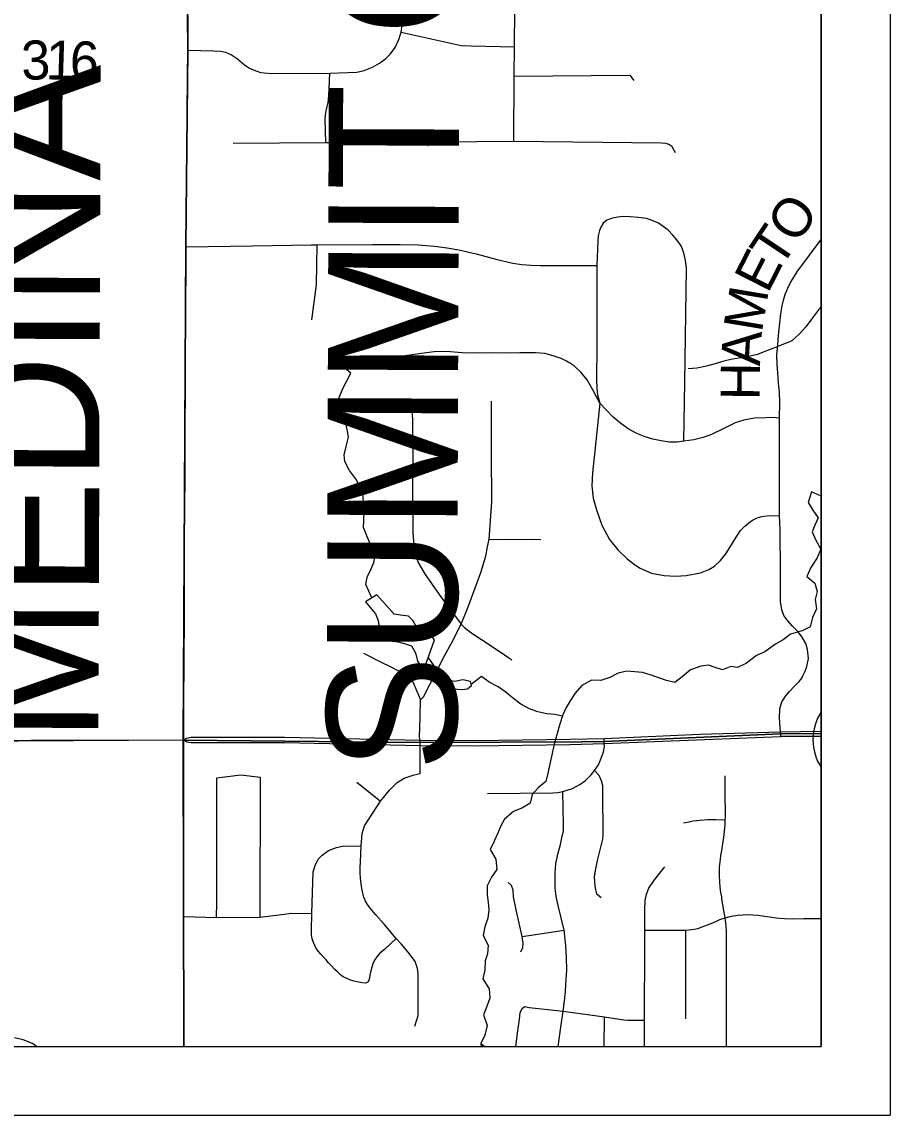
# Model space of a CAD drawing. Extents: x 0 to 34, y 0 to 22.
# Drawn here: x 7.738 to 9, y 14 to 15.589 of the extents above; entities that cross this region are included whole.
import ezdxf

# ---------------------------------------------------------------- set-up
doc = ezdxf.new("R2010")
doc.units = 0
for name, color, linetype in [('GM_X_Corporation', 7, 'Continuous'), ('GM_X_County_Road', 7, 'Continuous'), ('GM_X_County_Road_Text', 7, 'Continuous'), ('GM_X_County_Text', 7, 'Continuous'), ('GM_X_Minor_Lake', 7, 'Continuous'), ('GM_X_Minor_River', 7, 'Continuous'), ('GM_X_State_Route', 7, 'Continuous'), ('GM_X_State_Shield', 7, 'Continuous'), ('GM_X_Township_Road', 7, 'Continuous'), ('GM_X_Township_Road_Text', 7, 'Continuous'), ('SH_Data', 7, 'Continuous')]:
    doc.layers.add(name, color=color, linetype=linetype)

msp = doc.modelspace()

# ---------------------------------------------------------------- linework, layer by layer
at = {"layer": 'GM_X_Corporation'}
for points in [[(2.1, 20.9), (2.1, 14.1), (7.9734, 14.1), (7.9726, 14.5453), (7.9765, 15.2637), (7.9792, 15.5481), (7.979, 15.5988), (7.9808, 15.7192), (7.9807, 15.9078), (7.9821, 16.2487), (7.9825, 16.3395), (7.9818, 16.3982), (7.9825, 16.6077), (7.9838, 16.7968), (7.9877, 17.3871), (7.9891, 17.5498), (7.991, 17.7727), (7.9901, 18.1613)], [(7.9901, 18.1613), (7.991, 17.7727), (7.9891, 17.5498), (7.9877, 17.3871), (7.9838, 16.7968), (7.9825, 16.6077), (7.9818, 16.3982), (7.9825, 16.3395), (7.9821, 16.2487), (7.9807, 15.9078), (7.9808, 15.7192), (7.979, 15.5988), (7.9792, 15.5481), (7.9765, 15.2637), (7.9726, 14.5453), (7.9734, 14.1), (8.9, 14.1), (8.9, 20.9)], [(7.9901, 18.1613), (7.991, 17.7727), (7.9891, 17.5498), (7.9877, 17.3871), (7.9838, 16.7968), (7.9825, 16.6077), (7.9818, 16.3982), (7.9825, 16.3395), (7.9821, 16.2487), (7.9807, 15.9078), (7.9808, 15.7192), (7.979, 15.5988), (7.9792, 15.5481), (7.9765, 15.2637), (7.9726, 14.5453), (8.3169, 14.5418), (8.5518, 14.5426), (8.5844, 14.5431), (8.8409, 14.5545), (8.9, 14.5547), (8.9, 19.1229)], [(7.9901, 18.1613), (7.991, 17.7727), (7.9891, 17.5498), (7.9877, 17.3871), (7.9838, 16.7968), (7.9825, 16.6077), (7.9818, 16.3982), (7.9825, 16.3395), (7.9821, 16.2487), (7.9807, 15.9078), (7.9808, 15.7192), (7.979, 15.5988), (7.9792, 15.5481), (7.9765, 15.2637), (7.9726, 14.5453), (7.0871, 14.5429), (7.0197, 14.5427), (6.4941, 14.5412), (6.1476, 14.5397), (5.4644, 14.5374), (4.5212, 14.531)]]:
    msp.add_lwpolyline(points, dxfattribs=at)
for points in [[(2.8649, 14.1), (7.9734, 14.1), (7.9726, 14.5453), (7.0871, 14.5429), (7.0197, 14.5427), (6.4941, 14.5412), (6.1476, 14.5397), (5.4644, 14.5374), (4.5212, 14.531), (4.3772, 14.5296), (4.3422, 14.5307), (3.735, 14.5275), (3.3839, 14.5264), (3.3511, 14.525), (2.8655, 14.5214), (2.8638, 14.4461)], [(7.9734, 14.1), (8.9, 14.1), (8.9, 14.5547), (8.8409, 14.5545), (8.5844, 14.5431), (8.5518, 14.5426), (8.3169, 14.5418), (7.9726, 14.5453)]]:
    msp.add_lwpolyline(points, close=True, dxfattribs=at)
at = {"layer": 'GM_X_County_Road'}
for p, q in [((7.9798, 15.5778), (7.9801, 15.5987)), ((7.9793, 15.5479), (7.9798, 15.5778)), ((8.9, 14.5511), (8.8414, 14.5504))]:
    msp.add_line(p, q, dxfattribs=at)
for points in [[(7.9771, 15.2624), (7.9772, 15.2803), (7.9775, 15.328), (7.9777, 15.3954), (7.9782, 15.4454), (7.9783, 15.4576), (7.9788, 15.5089), (7.9793, 15.547), (7.9793, 15.5479)], [(8.8405, 14.7895), (8.8401, 14.8508), (8.8394, 14.8716), (8.8394, 15.0133), (8.8396, 15.0358), (8.8394, 15.0508), (8.8378, 15.0639), (8.8366, 15.0796), (8.8357, 15.0907), (8.8353, 15.1059), (8.8364, 15.1146), (8.8383, 15.1386), (8.8399, 15.1515), (8.8412, 15.1648), (8.8433, 15.1764), (8.8456, 15.1865), (8.8479, 15.1943), (8.8512, 15.2019), (8.8551, 15.2105), (8.8657, 15.2273), (8.9, 15.2729)], [(7.9738, 14.5455), (7.9738, 14.5968), (7.9742, 14.663), (7.9746, 14.723), (7.9746, 14.8291), (7.975, 14.8866), (7.9753, 14.9251), (7.9755, 14.9636), (7.9757, 15.0018), (7.9759, 15.0507), (7.9762, 15.1178), (7.9764, 15.1774), (7.9768, 15.2327), (7.9771, 15.2582), (7.9771, 15.2624)], [(8.8731, 14.6384), (8.8765, 14.6453), (8.879, 14.652), (8.8813, 14.6639), (8.8797, 14.6769), (8.8774, 14.6857), (8.8723, 14.6949), (8.8659, 14.7029), (8.8576, 14.7112), (8.8512, 14.7184), (8.8454, 14.7264), (8.8424, 14.7347), (8.8408, 14.7465), (8.8405, 14.7895)], [(8.8414, 14.5504), (8.8411, 14.5539), (8.8409, 14.5574), (8.8393, 14.5772), (8.8396, 14.5905), (8.8428, 14.601), (8.8484, 14.6096), (8.8539, 14.6156), (8.8607, 14.6231), (8.8677, 14.6306), (8.8717, 14.6354), (8.8731, 14.6384)], [(7.9735, 14.5256), (7.9738, 14.5415), (7.9738, 14.5455)], [(7.9736, 14.2886), (7.9737, 14.459), (7.9734, 14.5147), (7.9735, 14.5256)], [(7.9737, 14.1), (7.9737, 14.191), (7.9735, 14.2656), (7.9735, 14.2825), (7.9736, 14.2886)]]:
    msp.add_lwpolyline(points, dxfattribs=at)
at = {"layer": 'GM_X_Minor_Lake'}
for points in [[(8.338, 14.6911), (8.3322, 14.6983), (8.3246, 14.7009), (8.3177, 14.7031), (8.312, 14.7091), (8.3066, 14.7189), (8.3001, 14.7253), (8.2883, 14.7268), (8.2792, 14.7282), (8.2539, 14.7564), (8.2377, 14.746), (8.2522, 14.7287), (8.2561, 14.7188), (8.2578, 14.7052), (8.2632, 14.6954), (8.2731, 14.6897), (8.2849, 14.688), (8.2959, 14.685), (8.3046, 14.6824), (8.3101, 14.6719), (8.3132, 14.6597), (8.317, 14.6541), (8.3232, 14.6499)], [(8.3232, 14.6499), (8.338, 14.6911)], [(8.3502, 14.6331), (8.3568, 14.621)], [(8.3568, 14.621), (8.3655, 14.6196), (8.3773, 14.6189), (8.386, 14.6198), (8.3917, 14.6244), (8.3901, 14.6304), (8.3791, 14.6326), (8.3673, 14.6306), (8.3502, 14.6331)]]:
    msp.add_lwpolyline(points, dxfattribs=at)
at = {"layer": 'GM_X_Minor_River'}
for q in [(8.4112, 14.1), (8.4056, 14.1)]:
    msp.add_line((8.4051, 14.104), q, dxfattribs=at)
for points in [[(8.9, 15.1748), (8.896, 15.1706), (8.8859, 15.1572), (8.8773, 15.1461), (8.8679, 15.1353), (8.857, 15.1254), (8.8415, 15.1195), (8.8294, 15.1145), (8.8177, 15.1102), (8.8071, 15.1055), (8.7965, 15.1031), (8.7836, 15.1007), (8.7684, 15.0983), (8.7582, 15.0959), (8.7438, 15.0916), (8.7332, 15.0889), (8.7192, 15.0857), (8.7063, 15.0848)], [(8.2466, 14.7518), (8.2382, 14.7715), (8.24, 14.7821), (8.2452, 14.7932), (8.2497, 14.8035), (8.2515, 14.813), (8.2461, 14.8263), (8.2395, 14.8422), (8.2348, 14.8543), (8.2351, 14.8646), (8.2357, 14.8775), (8.2349, 14.8889), (8.234, 14.8999), (8.2301, 14.9101), (8.2247, 14.9237), (8.2143, 14.9369), (8.2077, 14.9502), (8.2065, 14.9597), (8.2098, 14.9737), (8.2127, 14.9855), (8.2111, 14.9969), (8.2084, 15.0075), (8.2029, 15.0204), (8.1987, 15.0314), (8.1982, 15.0409), (8.2045, 15.0561), (8.2097, 15.0657), (8.2161, 15.0787), (8.2065, 15.0869), (8.2, 15.1002), (8.1964, 15.1119)], [(8.9, 14.9005), (8.8988, 14.9004), (8.8855, 14.906), (8.8807, 14.8908), (8.8877, 14.8794), (8.8953, 14.8681), (8.8905, 14.8574), (8.8868, 14.8479), (8.8918, 14.8358), (8.8992, 14.8226), (8.894, 14.8103), (8.885, 14.7962), (8.879, 14.7832), (8.8905, 14.7731), (8.894, 14.7613), (8.8911, 14.7495), (8.8931, 14.7362), (8.8872, 14.7233), (8.8839, 14.7096), (8.8722, 14.7041), (8.8551, 14.699), (8.8446, 14.691), (8.8336, 14.6844), (8.8178, 14.6736), (8.8057, 14.6682), (8.7914, 14.657), (8.7781, 14.6508), (8.7686, 14.6522), (8.7565, 14.6472), (8.7455, 14.6505), (8.736, 14.6542), (8.725, 14.6526), (8.7099, 14.6471), (8.6978, 14.6371), (8.6873, 14.6287), (8.6751, 14.632), (8.6625, 14.6364), (8.6526, 14.6398), (8.6401, 14.6434), (8.6173, 14.6455), (8.6048, 14.6423), (8.5927, 14.6361), (8.5798, 14.6318), (8.5662, 14.6321), (8.5522, 14.6247), (8.5421, 14.6136), (8.535, 14.6022), (8.5293, 14.5926), (8.5245, 14.5819), (8.5197, 14.5667), (8.516, 14.5549), (8.5112, 14.5374), (8.5087, 14.5259), (8.5051, 14.5084), (8.5032, 14.4989), (8.4996, 14.4848), (8.4883, 14.476), (8.4796, 14.466), (8.4771, 14.4534), (8.4658, 14.4465), (8.4525, 14.4414), (8.4397, 14.4303), (8.4341, 14.4204), (8.4293, 14.4089), (8.4248, 14.3982), (8.4189, 14.386), (8.427, 14.372), (8.4286, 14.3572), (8.4208, 14.3458), (8.4144, 14.3332), (8.4142, 14.3206), (8.4158, 14.3092), (8.4166, 14.2982), (8.4152, 14.2864), (8.4112, 14.2739), (8.4086, 14.2609), (8.4159, 14.2473), (8.4149, 14.2344), (8.4116, 14.2245), (8.411, 14.2108), (8.408, 14.1982), (8.4173, 14.1835), (8.4185, 14.1698), (8.413, 14.1557), (8.4089, 14.1458), (8.4143, 14.1303), (8.4111, 14.1162), (8.4051, 14.104)], [(8.3514, 14.6329), (8.3288, 14.6657)], [(8.524, 14.5802), (8.5127, 14.5822), (8.5013, 14.5836), (8.488, 14.5865), (8.477, 14.5902), (8.4633, 14.5973), (8.453, 14.6052), (8.44, 14.6157), (8.4304, 14.6225), (8.4174, 14.6292), (8.406, 14.6378), (8.3912, 14.6261)], [(7.7597, 14.1), (7.7536, 14.1039), (7.7403, 14.1096), (7.7274, 14.1122)]]:
    msp.add_lwpolyline(points, dxfattribs=at)
at = {"layer": 'GM_X_State_Route'}
for p, q in [((8.7427, 14.5464), (8.8414, 14.5504)), ((8.8414, 14.5504), (8.9, 14.5511))]:
    msp.add_line(p, q, dxfattribs=at)
for points in [[(7.9738, 14.5455), (7.9777, 14.5482), (7.9837, 14.5493), (8.1198, 14.5494), (8.3171, 14.545), (8.3964, 14.5445), (8.5344, 14.5463), (8.5845, 14.5476), (8.7235, 14.5538), (8.8409, 14.5574), (8.9, 14.5581)], [(7.1508, 14.5437), (7.2108, 14.5436), (7.591, 14.5434), (7.6249, 14.5436), (7.7079, 14.5441), (7.7327, 14.5443), (7.9738, 14.5455)], [(7.9738, 14.5455), (7.9778, 14.5427), (7.9837, 14.5417), (8.1199, 14.5419), (8.3172, 14.5374), (8.3965, 14.5369), (8.5345, 14.5388), (8.5846, 14.54), (8.7427, 14.5464)]]:
    msp.add_lwpolyline(points, dxfattribs=at)
at = {"layer": 'GM_X_State_Shield'}
msp.add_line((8.9, 14.5049), (8.9, 14.5864), dxfattribs=at)
msp.add_arc((8.9622, 14.5457), 0.0744, 146.7554, 213.2446, dxfattribs=at)
at = {"layer": 'GM_X_Township_Road'}
for p, q in [((8.2251, 14.4841), (8.2592, 14.4566)), ((8.4655, 14.2595), (8.5263, 14.2687)), ((8.5845, 14.1), (8.5851, 14.1427)), ((8.6432, 14.1), (8.6432, 14.138))]:
    msp.add_line(p, q, dxfattribs=at)
for points in [[(8.4531, 15.4157), (8.4538, 15.5102), (8.454, 15.5528), (8.4547, 15.6078), (8.4549, 15.7237), (8.4568, 15.806)], [(7.9793, 15.5479), (8.017, 15.547), (8.0271, 15.5466), (8.0343, 15.545), (8.043, 15.5415), (8.0516, 15.5357), (8.0617, 15.527), (8.069, 15.5219), (8.0757, 15.5189), (8.0852, 15.5157), (8.1006, 15.5141), (8.1856, 15.5145), (8.2252, 15.5159), (8.2356, 15.5187), (8.2478, 15.5235), (8.2577, 15.5293), (8.2667, 15.5355), (8.2741, 15.5426), (8.2805, 15.5521), (8.2858, 15.5634), (8.2895, 15.5744), (8.2913, 15.588), (8.2911, 15.5972)], [(8.2895, 15.5744), (8.3635, 15.5579), (8.3764, 15.5551), (8.3913, 15.5546), (8.454, 15.5528)], [(8.1801, 15.4139), (8.1789, 15.448), (8.1794, 15.4542), (8.1803, 15.4599), (8.1817, 15.4662), (8.1831, 15.4719), (8.1838, 15.477), (8.1842, 15.4828), (8.1849, 15.4924), (8.1856, 15.5145)], [(8.4538, 15.5102), (8.6219, 15.5118), (8.6275, 15.5039)], [(8.0455, 15.4127), (8.1801, 15.4139), (8.2342, 15.4139)], [(8.328, 15.4095), (8.3386, 15.4136), (8.3457, 15.4148), (8.4531, 15.4157), (8.6673, 15.4134), (8.6735, 15.4127), (8.6784, 15.4113), (8.6825, 15.409), (8.6874, 15.3994)], [(8.7003, 14.9796), (8.7016, 15.0653), (8.7042, 15.231), (8.7028, 15.2425), (8.7, 15.2533), (8.6961, 15.2639), (8.6901, 15.2722), (8.6844, 15.2793), (8.6768, 15.2867), (8.6703, 15.2918), (8.6632, 15.2966), (8.6544, 15.3003), (8.6459, 15.3033), (8.6341, 15.3051), (8.6224, 15.3058), (8.612, 15.3063), (8.6044, 15.3054), (8.5966, 15.304), (8.5885, 15.301), (8.5832, 15.2964), (8.5798, 15.2906)], [(8.5798, 15.2906), (8.5775, 15.286), (8.5759, 15.2784), (8.5752, 15.2708), (8.5738, 15.2349), (8.574, 15.1019), (8.5733, 15.0851), (8.5733, 15.0695), (8.5736, 15.057), (8.5747, 15.0473), (8.5782, 15.0351), (8.5713, 14.9702), (8.5676, 14.9335), (8.5664, 14.9149), (8.5683, 14.8971), (8.5731, 14.8799), (8.5809, 14.8575), (8.5924, 14.837), (8.6044, 14.8218), (8.6178, 14.8087), (8.6286, 14.8002), (8.6369, 14.7949), (8.6533, 14.7879), (8.6717, 14.7845), (8.6883, 14.7833), (8.7037, 14.7843), (8.7242, 14.7882), (8.7364, 14.793), (8.745, 14.7981), (8.7535, 14.8061), (8.7611, 14.8158), (8.7694, 14.829), (8.7763, 14.8402), (8.7825, 14.8499), (8.789, 14.8561), (8.7945, 14.8612), (8.8002, 14.8651), (8.8069, 14.8681), (8.8134, 14.87), (8.821, 14.8713), (8.8394, 14.8716)], [(7.9771, 15.2624), (8.0736, 15.2639), (8.1584, 15.2653), (8.1674, 15.2653), (8.2476, 15.2657), (8.2881, 15.2655), (8.3148, 15.265), (8.3379, 15.263), (8.3561, 15.2607), (8.3734, 15.2577), (8.3982, 15.2519), (8.4289, 15.2439), (8.4515, 15.2386), (8.4646, 15.2365), (8.4782, 15.2358), (8.492, 15.2353), (8.5738, 15.2349)], [(8.1598, 15.1563), (8.1665, 15.2071), (8.1674, 15.2653)], [(8.8394, 15.0133), (8.8297, 15.0139), (8.8196, 15.0137), (8.8028, 15.013), (8.7876, 15.0103), (8.7747, 15.0063), (8.7585, 14.998), (8.7403, 14.9895), (8.7281, 14.9851), (8.7145, 14.9815), (8.7003, 14.9796), (8.6906, 14.9782), (8.6793, 14.9785), (8.6675, 14.9801), (8.6551, 14.9826), (8.6438, 14.9858), (8.6318, 14.9911), (8.6194, 14.9976), (8.6081, 15.0057), (8.5977, 15.0144), (8.5874, 15.0255), (8.5782, 15.0351), (8.5683, 15.0536), (8.5595, 15.069), (8.5505, 15.0801), (8.5415, 15.0886), (8.5355, 15.0925), (8.5296, 15.096), (8.522, 15.1001), (8.5104, 15.1038), (8.498, 15.107), (8.4846, 15.1079), (8.4618, 15.1079), (8.4434, 15.1077), (8.4215, 15.1082), (8.3982, 15.1077), (8.378, 15.1082), (8.3552, 15.1102), (8.3372, 15.1098), (8.319, 15.107), (8.2953, 15.104), (8.2702, 15.1022)], [(8.3172, 14.5374), (8.3172, 14.5412), (8.3171, 14.545), (8.316, 14.5491), (8.3169, 14.5786), (8.3173, 14.6038), (8.3218, 14.6083), (8.3312, 14.6258), (8.3406, 14.6447), (8.3522, 14.6679), (8.3625, 14.6861), (8.3764, 14.7135), (8.3867, 14.739), (8.3999, 14.7741), (8.4052, 14.7889), (8.4123, 14.8124), (8.4151, 14.8262), (8.4171, 14.8375), (8.421, 14.8909), (8.4206, 14.9623), (8.4208, 15.0183), (8.4206, 15.0381)], [(8.3054, 15.031), (8.3063, 14.9642), (8.3061, 14.9082), (8.3066, 14.8469), (8.3084, 14.8214), (8.3105, 14.8124), (8.3146, 14.8025), (8.3245, 14.7861), (8.3473, 14.7534), (8.3764, 14.7135), (8.3819, 14.7085), (8.3923, 14.7006), (8.4063, 14.6912), (8.4289, 14.6764), (8.4503, 14.6619)], [(8.4171, 14.8375), (8.4367, 14.837), (8.4793, 14.8372), (8.4922, 14.8366)], [(8.2348, 14.6717), (8.2605, 14.6584), (8.2734, 14.6523), (8.2863, 14.6456), (8.2953, 14.64), (8.3017, 14.635), (8.3068, 14.629), (8.3173, 14.6038)], [(8.4151, 14.4674), (8.51, 14.4684), (8.5169, 14.4691), (8.5245, 14.4705), (8.5383, 14.4746), (8.5491, 14.4804), (8.5572, 14.4864), (8.5657, 14.4947), (8.5703, 14.5009), (8.5763, 14.5094), (8.5802, 14.5189), (8.5835, 14.5283), (8.585, 14.5358), (8.5846, 14.54), (8.5846, 14.5426), (8.5845, 14.5476)], [(8.2892, 14.2489), (8.2823, 14.2567), (8.2648, 14.2774), (8.2527, 14.2912), (8.2443, 14.3008), (8.2406, 14.306), (8.2377, 14.3109), (8.2352, 14.3169), (8.2335, 14.3228), (8.2322, 14.3294), (8.2313, 14.3368), (8.2305, 14.344), (8.23, 14.3526), (8.23, 14.36), (8.2301, 14.3681), (8.2312, 14.3912), (8.2329, 14.4093), (8.2362, 14.4204), (8.2423, 14.4303), (8.2592, 14.4566), (8.2727, 14.4726), (8.2834, 14.4837), (8.2937, 14.4899), (8.3081, 14.4948), (8.3171, 14.4964), (8.3172, 14.5374)], [(8.0212, 14.2872), (8.0216, 14.3093), (8.0217, 14.4903), (8.0562, 14.4948), (8.0845, 14.4911), (8.0841, 14.2876)], [(8.58, 14.3161), (8.574, 14.3214), (8.5715, 14.333), (8.5706, 14.3468), (8.5722, 14.3578), (8.5745, 14.3701), (8.5809, 14.3952), (8.5823, 14.4012), (8.583, 14.4078), (8.5828, 14.4134), (8.5825, 14.4634), (8.5823, 14.4788), (8.5807, 14.4859), (8.577, 14.4935), (8.5703, 14.5009)], [(8.7605, 14.4294), (8.7606, 14.4332), (8.7606, 14.4371), (8.7603, 14.4668), (8.7601, 14.4932)], [(8.5249, 14.1512), (8.5267, 14.166), (8.5281, 14.1796), (8.5287, 14.1899), (8.53, 14.2111), (8.5296, 14.2288), (8.5286, 14.2468), (8.5263, 14.2687), (8.5175, 14.3048), (8.5149, 14.3176), (8.5134, 14.3305), (8.5131, 14.3414), (8.513, 14.3519), (8.5143, 14.3652), (8.5171, 14.3795), (8.5208, 14.3936), (8.5231, 14.403), (8.5251, 14.4132), (8.5254, 14.422), (8.5245, 14.4705)], [(8.6999, 14.4247), (8.7099, 14.4269), (8.7138, 14.4276), (8.7192, 14.4284), (8.7236, 14.4289), (8.7297, 14.4295), (8.7344, 14.4297), (8.7401, 14.4299), (8.7431, 14.4299), (8.7461, 14.4298), (8.7605, 14.4294)], [(8.7603, 14.287), (8.7576, 14.303), (8.7556, 14.3151), (8.7552, 14.3175), (8.7542, 14.3235), (8.7531, 14.331), (8.7523, 14.3397), (8.7519, 14.3472), (8.7519, 14.3541), (8.7522, 14.3608), (8.7528, 14.3677), (8.7542, 14.3776), (8.7553, 14.3845), (8.7569, 14.3942), (8.7583, 14.4037), (8.7594, 14.4125), (8.7602, 14.4225), (8.7605, 14.4294)], [(8.2823, 14.2567), (8.265, 14.2409), (8.2586, 14.2355), (8.2539, 14.2301), (8.2507, 14.2251), (8.248, 14.2197), (8.2466, 14.215), (8.2451, 14.2098), (8.2441, 14.2034), (8.2429, 14.1973), (8.2416, 14.1938), (8.2382, 14.1918), (8.2327, 14.1923), (8.2281, 14.1933), (8.2212, 14.1948), (8.2157, 14.1963), (8.2096, 14.199), (8.2051, 14.2012), (8.2012, 14.2039), (8.1967, 14.2084), (8.193, 14.2118), (8.1881, 14.217), (8.1839, 14.2212), (8.1805, 14.2259), (8.177, 14.2293), (8.1726, 14.234), (8.1696, 14.2375), (8.1659, 14.2424), (8.1639, 14.2466), (8.162, 14.251), (8.16, 14.2564), (8.1593, 14.2621), (8.1593, 14.2688), (8.1597, 14.293), (8.1614, 14.3538), (8.1642, 14.3629), (8.1688, 14.3719), (8.1745, 14.3781), (8.184, 14.3846), (8.1955, 14.3892), (8.2062, 14.3916), (8.2312, 14.3912)], [(8.6434, 14.2691), (8.6434, 14.2991), (8.644, 14.3121), (8.6461, 14.3212), (8.6495, 14.3297), (8.6577, 14.342), (8.6726, 14.3611)], [(8.4632, 14.2375), (8.4664, 14.2438), (8.4669, 14.2496), (8.4655, 14.2595), (8.4563, 14.2982), (8.4528, 14.3175), (8.4524, 14.3272), (8.4498, 14.3337), (8.445, 14.3383)], [(7.9736, 14.2886), (8.0212, 14.2872), (8.0841, 14.2876), (8.112, 14.2913), (8.1301, 14.2934), (8.1597, 14.293)], [(8.6434, 14.2691), (8.695, 14.2691), (8.7032, 14.269), (8.7153, 14.2702), (8.7207, 14.2715), (8.727, 14.2738), (8.7422, 14.2795), (8.7523, 14.2842), (8.7603, 14.287), (8.7697, 14.2894), (8.7786, 14.2908), (8.7933, 14.2918), (8.8075, 14.2909), (8.8245, 14.2885), (8.8345, 14.287), (8.8465, 14.2858), (8.8574, 14.2854), (8.8743, 14.2856), (8.9, 14.2859)], [(8.7622, 14.1), (8.7622, 14.2565), (8.7622, 14.2663), (8.7617, 14.275), (8.7603, 14.287)], [(8.6432, 14.138), (8.6432, 14.1504), (8.6433, 14.2376), (8.6434, 14.2691)], [(8.703, 14.1399), (8.7031, 14.1935), (8.7032, 14.2274), (8.7032, 14.269)], [(8.3094, 14.1292), (8.3141, 14.1448), (8.3143, 14.1492), (8.3143, 14.1551), (8.3143, 14.2059), (8.3133, 14.2131), (8.3114, 14.219), (8.3096, 14.2234), (8.3044, 14.2308), (8.2995, 14.237), (8.2892, 14.2489)], [(8.4561, 14.1), (8.4591, 14.1225), (8.4615, 14.1396), (8.4625, 14.1489), (8.4648, 14.1544), (8.4685, 14.1577), (8.4754, 14.1567), (8.5249, 14.1512)], [(8.5176, 14.1), (8.5214, 14.1279), (8.5249, 14.1512)], [(8.5249, 14.1512), (8.5851, 14.1427), (8.6129, 14.1385)], [(8.6129, 14.1385), (8.6189, 14.1381), (8.6432, 14.138)]]:
    msp.add_lwpolyline(points, dxfattribs=at)
at = {"layer": 'SH_Data'}
for p, q in [((9, 21), (9, 14)), ((8.9, 20.9), (8.9, 14.1)), ((2.1, 14.1), (8.9, 14.1)), ((2, 14), (9, 14))]:
    msp.add_line(p, q, dxfattribs=at)

# ---------------------------------------------------------------- texts
at = {"layer": 'GM_X_County_Road_Text'}
for s, rotation, p in [('O', 54.9014, (8.864, 15.2645)), ('T', 56.2945, (8.8406, 15.2294)), ('E', 62.9941, (8.8222, 15.1931)), ('M', 80.5231, (8.8135, 15.1366)), ('A', 86.727, (8.8108, 15.0883)), ('H', 89.4099, (8.8103, 15.039))]:
    msp.add_text(s, height=0.0568, rotation=rotation, dxfattribs=at).set_placement(p)
at = {"layer": 'GM_X_County_Text'}
for s, p in [('MEDINA COUNTY', (7.8494, 14.542)), ('SUMMIT COUNTY', (8.3702, 14.4995))]:
    msp.add_text(s, height=0.189394, rotation=89.8023, dxfattribs=at).set_placement(p)
at = {"layer": 'GM_X_Township_Road_Text'}
for s, rotation, p in [('3', 1.6342, (7.738, 15.5048)), ('1', 358.1992, (7.7721, 15.5058)), ('6', 358.33, (7.8072, 15.5046))]:
    msp.add_text(s, height=0.0568, rotation=rotation, dxfattribs=at).set_placement(p)

doc.saveas('drawing.dxf')
